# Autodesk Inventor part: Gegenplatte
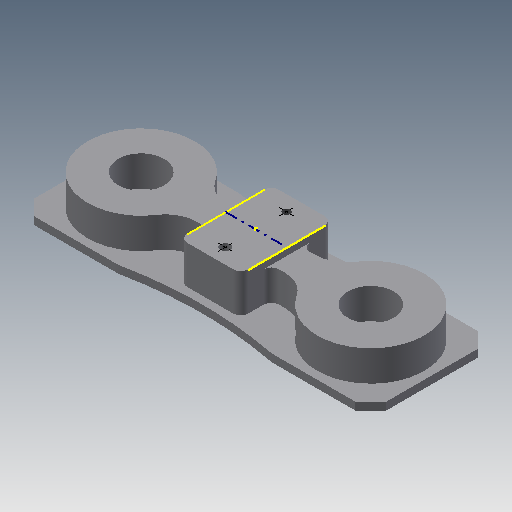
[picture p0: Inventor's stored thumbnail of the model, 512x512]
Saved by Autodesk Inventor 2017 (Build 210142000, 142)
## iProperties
Created: 2015-04
Part Number: Gegenplatte
Material: Generisch
Document SubType Name: Modeling
Designer: e_krauts
Density: 1 g/cm^3
Appearance: Vorgabe
Author: e_krauts
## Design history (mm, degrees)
sketch "Skizze1"
  geometry: L1 (0, 122.557)-(0, -117.957); L2 (-201.086, 0)-(208.971, 0); L3 (105, -40)-(-105, -40); L4 (-115, -30)-(-115, 30); L5 (-105, 40)-(105, 40); L6 (115, 30)-(115, -30); L7 (115, -40)-(-115, 40); L8 (-115, -40)-(115, 40); L9 (-115, 30)-(-105, 40); L10 (105, 40)-(115, 30); L11 (115, -30)-(105, -40); L12 (-105, -40)-(-115, -30); 2 further points
  constraints: 24 end point, 8 point on line, 2 midpoint, 2 parallel, 2 perpendicular, 1 coincident, 1 horizontal, 1 vertical
  dimensions: "d0" = 230 distance between parallel lines of L6 L4; "d1" = 80 distance between parallel lines of L3 L5; "d2" = 10 distance of L4.end L7.end; "d3" = 10 distance of L5.start L7.end (= d2); "d4" = 10 distance of L5.end L8.end (= d2); "d5" = 10 distance of L6.start L8.end (= d4); "d6" = 10 distance of L6.end L7.start (= d2); "d7" = 10 distance of L3.start L7.start (= d6); "d8" = 10 distance of L3.end L8.start (= d2); "d9" = 10 distance of L4.start L8.start (= d8)
extrude "Extrusion1" new body sketch "Skizze1" distance "d10" = 5; taper "d11" = 0 deg
sketch "Skizze2"
  geometry: L1 (-105, 40)-(105, 40) reference; L2 (0, 53.954)-(0, -63.401) reference; L3 (-137.09, 0)-(142.128, 0) reference; L4 (0, 10)-(-28.902, 10); L5 (0, -10)-(-28.902, -10); L6 (137.09, 0)-(-142.128, 0); L7 (0, -10)-(28.902, -10); L8 (0, 10)-(28.902, 10); A1 r 20 centre (-28.902, 30) between (-45.665, 19.091) and (-28.902, 10); A2 r 35 centre (-75, 0) between (-45.665, 19.091) and (-110, 0); A3 r 35 centre (-75, 0) between (-110, 0) and (-45.665, -19.091); A4 r 20 centre (-28.902, -30) between (-28.902, -10) and (-45.665, -19.091); A5 r 20 centre (28.902, 30) between (28.902, 10) and (45.665, 19.091); A6 r 20 centre (28.902, -30) between (45.665, -19.091) and (28.902, -10); A7 r 35 centre (75, 0) between (45.665, -19.091) and (110, 0); A8 r 35 centre (75, 0) between (110, 0) and (45.665, 19.091); 1 further point
  constraints: 16 point on circle, 14 end point, 14 symmetric about line, 8 centre point, 5 point on line, 2 perpendicular, 2 tangent, 1 horizontal, 1 parallel, 1 vertical, 6 other
  dimensions: "d18" = 20 diameter of L4 L3; "d19" = 150 diameter of A2.centre L2; "d20" = 20 radius of A1; "d21" = 35 radius of A2
extrude "Extrusion2" join sketch "Skizze2" distance "d22" = 20; taper "d23" = 0 deg; dims "d60" = 5, "d61" = 0
sketch "Skizze3"
  geometry: C1 r 15 at (-75, 0); C2 r 15 at (75, 0); A1 r 35 centre (-75, 0) between (-45.665, 19.091) and (-45.665, -19.091) reference; A2 r 35 centre (75, 0) between (45.665, -19.091) and (45.665, 19.091) reference; 1 further point
  constraints: 2 centre point, 2 coincident, 1 equal radius
  dimensions: "d24" = 30 diameter of C1
extrude "Extrusion3" cut sketch "Skizze3" stored distance "d25" = 20; taper "d26" = 0 deg
sketch "Skizze4"
  geometry: L1 (15, -30)-(-15, -30); L2 (-20, -25)-(-20, 25); L3 (-15, 30)-(15, 30); L4 (20, 25)-(20, -25); L5 (20, -30)-(-20, 30); L6 (-20, -30)-(20, 30); A1 r 5 centre (-15, 25) between (-15, 30) and (-20, 25); A2 r 5 centre (15, 25) between (20, 25) and (15, 30); A3 r 5 centre (15, -25) between (15, -30) and (20, -25); A4 r 5 centre (-15, -25) between (-20, -25) and (-15, -30); 1 further point
  constraints: 12 end point, 8 point on circle, 8 point on line, 8 tangent, 4 centre point, 3 equal radius, 2 midpoint, 2 parallel, 1 horizontal, 1 perpendicular
  dimensions: "d27" = 40 distance between parallel lines of L4 L2; "d28" = 60 distance between parallel lines of L1 L3; "d29" = 5 radius of A1
extrude "Extrusion4" join sketch "Skizze4" distance "d31" = 25; taper "d32" = 0 deg; dims "d65" = 5, "d66" = 0
sketch "Skizze8"
  geometry: L1 (-20, 25)-(-20, -25) reference; L2 (20, -25)-(20, 25) reference; L3 (-20, 0)-(20, 0); 3 further points
  constraints: 2 end point, 2 midpoint, 1 symmetric about line
hole "Bohrung2" sketch "Skizze8" diameter "d68" = 4.917; stored, may be unused: countersink angle "d72" = 90 deg, drill point angle "d74" = 118 deg; dims "d69" = 20, "d70" = 4, "d71" = 2, "d73" = 25
hole "Bohrung3" diameter "d77" = 6.6; stored, may be unused: countersink angle "d81" = 90 deg, drill point angle "d83" = 118 deg; dims "d75" = 20, "d76" = 20, "d78" = 20, "d79" = 11, "d80" = 6.4, "d82" = 25
sketch "Skizze9"
  geometry: L1 (105, 40)-(-105, 40) reference; L2 (115, -30)-(115, 30) reference; L3 (-49.749, 40)-(49.749, 40); L4 (0, 296.061)-(0, 191.763); L5 (-85.317, 0)-(97.839, 0); L6 (105, -40)-(-105, -40); A1 r 250 centre (0, 285) between (-49.749, 40) and (49.749, 40); A2 r 250 centre (0, -285) between (49.749, -40) and (-49.749, -40); 1 further point
  constraints: 8 end point, 4 point on circle, 4 point on line, 4 symmetric about line, 3 perpendicular, 2 centre point, 1 other
  dimensions: "d84" = 5 distance edge to line of A1 L3; "d85" = 250 radius of A1
extrude "Extrusion7" cut sketch "Skizze9" stored distance "d86" = 10; taper "d87" = 0 deg
fillet "Rundung6" dims "d88" = 5
fillet "Rundung7" dims "d89" = 30
node "Volumenkörper1"
